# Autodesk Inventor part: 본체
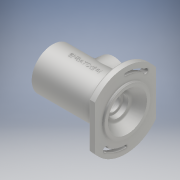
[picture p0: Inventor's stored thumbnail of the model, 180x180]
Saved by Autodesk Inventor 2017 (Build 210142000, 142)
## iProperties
Part Number: 본체
Material: 알루미늄 6061
Document SubType Name: Modeling
Designer: MRC
Density: 2.7 g/cm^3
Appearance: 알루미늄 - 평지
Author: MRC
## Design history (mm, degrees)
sketch "스케치1"
  geometry: L1 (47, 33.985)-(47, -33.985); L2 (-47, -33.985)-(-47, 33.985); A1 r 58 centre (0, 0) between (47, 33.985) and (-47, 33.985); A2 r 58 centre (0, 0) between (-47, -33.985) and (47, -33.985); 1 further point
  constraints: 4 end point, 4 point on circle, 2 centre point, 1 coincident, 1 parallel, 1 vertical
  dimensions: "d3" = 58 radius of A2; "d4" = 58 radius of A1; "d5" = 94 distance between parallel lines of L1 L2; "d6" = 47 distance from line of point (0, 0) L1
extrude "돌출1" new body sketch "스케치1" distance "d7" = 10; taper "d8" = 0 deg
sketch "스케치2"
  geometry: L1 (33.985, -47)-(-33.985, -47) reference; L2 (-33.985, 47)-(33.985, 47) reference; C1 r 36 at (0, 0); A1 r 58 centre (0, 0) between (33.985, -47) and (33.985, 47) reference; A2 r 58 centre (0, 0) between (-33.985, 47) and (-33.985, -47) reference; 1 further point
  constraints: 1 centre point, 1 coincident
  dimensions: "d9" = 72 diameter of C1
extrude "돌출2" join sketch "스케치2" distance "d10" = 3; taper "d11" = 0 deg
chamfer "모따기1" distance "d26" = 1; stored, may be unused: second distance "d27" = 2, angle "d28" = 45 deg
sketch "스케치4"
  geometry: L1 (-33.985, -47)-(33.985, -47) reference; L2 (33.985, 47)-(-33.985, 47) reference; C1 r 32 at (0, 0); A1 r 58 centre (0, 0) between (33.985, -47) and (33.985, 47) reference; A2 r 58 centre (0, 0) between (-33.985, 47) and (-33.985, -47) reference; 1 further point
  constraints: 1 centre point, 1 coincident
  dimensions: "d29" = 64 diameter of C1
extrude "돌출4" join sketch "스케치4" distance "d30" = 102; taper "d31" = 0 deg
fillet "모깎기1" dims "d32" = 3
node "작업 평면1"
node "작업 평면2"
sketch "스케치10"
  geometry: L1 (3, 35)-(3, -35) reference; L2 (3, 0)-(-112, 0); L3 (3, 30)-(-9.744, 20.897); L4 (-11, 18.456)-(-11, 15.404); L5 (-11.7, 15)-(-17.8, 15); L6 (-18.3, 14.5)-(-18.3, 11); L7 (-18.3, 11)-(-21, 11); L8 (-21, 11)-(-21, 12); L9 (-37, 18.5)-(-37, 24); L10 (-47.665, 26.047)-(-47.665, 25.836); L11 (-40, 27)-(-72, 27); L12 (-75, 24)-(-75, 18.5); L13 (-76, 17.5)-(-86, 17.5); L14 (-86, 17.5)-(-86, 18.5); L15 (-86, 18.5)-(-87.75, 18.5); L16 (-87.75, 18.5)-(-87.75, 17.5); L17 (-87.75, 17.5)-(-89, 17.5); L18 (-90, 18.5)-(-90, 19.5); L19 (-93, 22.5)-(-101, 22.5); L20 (-101, 22.5)-(-101, 24); L21 (-101, 24)-(-104, 24); L22 (-104, 24)-(-104, 22.5); L23 (-104, 22.5)-(-112, 22.5); L24 (-112, 32)-(-112, -32) reference; L25 (-11.7, 15)-(-11, 15.404); L26 (-76, 17.5)-(-75, 18.5); L27 (-89, 17.5)-(-90, 18.5); L28 (-112, 22.5)-(-112, 0); L29 (3, 30)-(3, 0); L30 (2, -36)-(2, 36) reference; L31 (-24, 15)-(-26, 15); L32 (-26, 15)-(-26, 16.9); L33 (-26.6, 17.5)-(-36, 17.5); L34 (-37, 18.5)-(-36, 17.5); A1 r 3 centre (-8, 18.456) between (-9.744, 20.897) and (-11, 18.456); A2 r 0.5 centre (-17.8, 14.5) between (-17.8, 15) and (-18.3, 14.5); A3 r 3 centre (-24, 12) between (-21, 12) and (-24, 15); A4 r 3 centre (-40, 24) between (-37, 24) and (-40, 27); A5 r 3 centre (-72, 24) between (-72, 27) and (-75, 24); A6 r 3 centre (-93, 19.5) between (-90, 19.5) and (-93, 22.5); A7 r 0.6 centre (-26.6, 16.9) between (-26, 16.9) and (-26.6, 17.5); 12 further points
  constraints: 62 end point, 24 point on line, 15 perpendicular, 14 point on circle, 13 tangent, 7 centre point, 4 horizontal, 2 vertical, 1 equal radius, 1 midpoint, 1 parallel
  dimensions: "d45" = 60 diameter of L3.start L2; "d46" = 40 diameter of point (-11, 20) L2; "d47" = 14 horizontal distance of point (-11, 20) L3.start; "d48" = 115 distance of L2.start L2.end; "d49" = 30 diameter of L5 L2; "d50" = 22 diameter of L7 L2; "d51" = 7.3 distance of point (-11, 15) point (-18.3, 15); "d55" = 54 diameter of L11 L2; "d57" = 35 diameter of L13 L2; "d58" = 11 distance of point (-75, 17.5) L13.end; "d59" = 1.75 distance of L14.end L15.end; "d60" = 37 diameter of L15 L2; "d61" = 4 distance between parallel lines of L18 L14; "d62" = 45 diameter of L19 L2; "d63" = 48 diameter of L21 L2; "d64" = 3 distance between parallel lines of L20 L22; "d65" = 8 distance from line of L22 L23.end; "d66" = 45 diameter of L23 L2; "d67" = 3 radius of A1; "d68" = 0.5 radius of A2; "d69" = 0.7 distance of L5.start point (-11, 15); "d70" = 30 deg angle of L5 L25; "d71" = 3 radius of A3; "d74" = 3 radius of A4 (derived); "d75" = 1 distance of L13.start point (-75, 17.5); "d76" = 1 distance of L12.end point (-75, 17.5) (= d75); "d77" = 1 distance of L17.end point (-90, 17.5) (= d75); "d78" = 1 distance of L18.start point (-90, 17.5) (= d77); "d79" = 3 radius of A6 (derived); "d148" = 5 distance between parallel lines of L8 L32; "d149" = 11 distance between parallel lines of L32 L9; "d150" = 29 distance between parallel lines of L1 L32; "d151" = 30 diameter of L31 L2; "d152" = 35 diameter of L33 L2; "d153" = 38 distance between parallel lines of L9 L12; "d155" = 0.6 radius of A7; "d156" = 1 distance of L9.start point (-37, 17.5); "d157" = 1 distance of L33.end point (-37, 17.5) (= d156)
revolve "회전1" sketch "스케치10" stored, may be unused: angle "d80" = 90 deg
feature "스레드1" dims "d81" = 10, "d82" = 0
node "작업 평면3"
sketch "스케치12"
  geometry: L1 (-3, -35)-(-3, 35) reference; L2 (112, -32)-(112, 32) reference; C1 r 25 at (56, 0); 1 further point
  constraints: 1 centre point
  dimensions: "d99" = 50 diameter of C1; "d154" = 56 distance from line of L2 C1.centre
extrude "돌출8" join sketch "스케치12" stored distance "d101" = 102; taper "d102" = 5 deg
hole "구멍2" diameter "d105" = 32; stored, may be unused: countersink angle "d109" = 90 deg, drill point angle "d111" = 118 deg; dims "d103" = 10, "d104" = 10, "d106" = 6, "d107" = 4, "d108" = 2, "d110" = 20
fillet "모깎기3" dims "d112" = 3
chamfer "모따기2" distance "d113" = 1; stored, may be unused: second distance "d114" = 2, angle "d115" = 45 deg
sketch "스케치13"
  geometry: C1 r 25 at (0, 0) reference; C2 r 17 at (0, 0) reference; A1 r 20.5 centre (0, 0) between (0, -20.5) and (0, 20.5); 1 further point
  constraints: 2 point on circle, 1 centre point, 1 coincident
  dimensions: "d116" = 41 diameter of A1
hole "구멍3" sketch "스케치13" at (0, -20.5), (0, 20.5) diameter "d117" = 2.621; stored, may be unused: countersink angle "d121" = 90 deg, drill point angle "d123" = 118 deg; dims "d118" = 6, "d119" = 4, "d120" = 2, "d122" = 8
sketch "스케치14"
  geometry: L1 (0, 0)-(-36.77, 30.854); L2 (0, 0)-(48, 0); L3 (0, 0)-(36.77, -30.854); L4 (0, 0)-(48, 0); L5 (0, 0)-(0, 37.337); L6 (0, 0)-(36.77, 30.854); A1 r 2.25 centre (36.77, 30.854) between (38.494, 32.3) and (35.047, 29.408); A2 r 45.75 centre (0, 0) between (45.75, 0) and (35.047, 29.408); A3 r 50.25 centre (0, 0) between (50.25, 0) and (38.494, 32.3); A4 r 2.25 centre (48, 0) between (45.75, 0) and (50.25, 0); A5 r 45.75 centre (0, 0) between (-45.75, 0) and (-35.047, -29.408); A6 r 50.25 centre (0, 0) between (-50.25, 0) and (-38.494, -32.3); A7 r 2.25 centre (-48, 0) between (-45.75, 0) and (-50.25, 0); A8 r 2.25 centre (-36.77, -30.854) between (-38.494, -32.3) and (-35.047, -29.408); 1 further point
  constraints: 16 point on circle, 12 end point, 8 centre point, 2 coincident, 2 equal length, 2 horizontal, 1 point on line, 1 symmetric about line, 1 vertical
  dimensions: "d125" = 140 deg angle of L2 L1; "d130" = 40 deg angle of L3 L4
extrude "돌출9" cut sketch "스케치14" distance "d131" = 102; taper "d132" = 0 deg
sketch "스케치16"
  geometry: L1 (-33, -44)-(33, -44) reference; L2 (33, 44)-(-33, 44) reference; C1 r 20.692 at (0, 0) reference; C2 r 35 at (0, 0) reference; C3 r 4 at (36.77, 30.854); C4 r 4 at (-36.77, -30.854); A1 r 2.25 centre (-48, 0) between (-45.75, 0) and (-50.25, 0) reference; A2 r 50.25 centre (0, 0) between (-50.25, 0) and (-38.494, -32.3) reference; A3 r 2.25 centre (-36.77, -30.854) between (-38.494, -32.3) and (-35.047, -29.408) reference; A4 r 45.75 centre (0, 0) between (-45.75, 0) and (-35.047, -29.408) reference; A5 r 45.75 centre (0, 0) between (45.75, 0) and (35.047, 29.408) reference; A6 r 2.25 centre (48, 0) between (45.75, 0) and (50.25, 0) reference; A7 r 50.25 centre (0, 0) between (50.25, 0) and (38.494, 32.3) reference; A8 r 2.25 centre (36.77, 30.854) between (38.494, 32.3) and (35.047, 29.408) reference; A9 r 55 centre (0, 0) between (33, -44) and (33, 44) reference; A10 r 55 centre (0, 0) between (-33, 44) and (-33, -44) reference; 1 further point
  constraints: 2 centre point, 2 coincident
  dimensions: "d141" = 8 diameter of C3; "d142" = 8 diameter of C4
extrude "돌출11" cut sketch "스케치16" stored distance "d143" = 4.4; taper "d144" = 0 deg
node "작업 평면4"
sketch "스케치17"
  geometry: L1 (10, 47)-(10, -47) reference; 3 further points
  constraints: 1 horizontal alignment, 1 midpoint, 1 other
  dimensions: "d145" = 62 distance from line of L1 point (-52, 0)
feature "엠보싱1" sketch "스케치17" dims "d3" = 58, "d4" = 58, "d5" = 94, "d6" = 47, "d146" = 0.5, "d147" = 0
sketch "스케치18"
  geometry: L1 (-33, -44)-(33, -44) reference; L2 (33, 44)-(-33, 44) reference; C1 r 20.692 at (0, 0) reference; C2 r 35 at (0, 0) reference; A1 r 4 centre (-36.77, -30.854) between (-40.58, -29.636) and (-37.033, -26.862) reference; A2 r 45.75 centre (0, 0) between (-45.75, 0) and (-37.033, -26.862) reference; A3 r 2.25 centre (-48, 0) between (-45.75, 0) and (-50.25, 0) reference; A4 r 50.25 centre (0, 0) between (-50.25, 0) and (-40.58, -29.636) reference; A5 r 4 centre (36.77, 30.854) between (40.58, 29.636) and (37.033, 26.862) reference; A6 r 45.75 centre (0, 0) between (45.75, 0) and (37.033, 26.862) reference; A7 r 2.25 centre (48, 0) between (45.75, 0) and (50.25, 0) reference; A8 r 50.25 centre (0, 0) between (50.25, 0) and (40.58, 29.636) reference; A9 r 55 centre (0, 0) between (33, -44) and (33, 44) reference; A10 r 55 centre (0, 0) between (-33, 44) and (-33, -44) reference; A11 r 4 centre (36.77, 30.854) between (39.834, 33.425) and (33.706, 28.283); A12 r 4 centre (48, 0) between (44, 0) and (52, 0); A13 r 4 centre (-48, 0) between (-44, 0) and (-52, 0); A14 r 4 centre (-36.77, -30.854) between (-39.834, -33.425) and (-33.706, -28.283); A15 r 52 centre (0, 0) between (-52, 0) and (-39.834, -33.425); A16 r 44 centre (0, 0) between (-44, 0) and (-33.706, -28.283); A17 r 52 centre (0, 0) between (52, 0) and (39.834, 33.425); A18 r 44 centre (0, 0) between (44, 0) and (33.706, 28.283); 1 further point
  constraints: 20 point on circle, 8 centre point, 5 coincident, 1 concentric
  dimensions: "d158" = 8 diameter of A12; "d159" = 8 diameter of A13
extrude "돌출12" cut sketch "스케치18" distance "d165" = 4.4; taper "d166" = 0 deg
node "솔리드1"
node "투영된 루프1"
node "투영된 루프2"
node "투영된 루프5"
node "절단 모서리 투영4"
node "절단 모서리 투영5"
other parameters: "d0" = 58, "d12" = 96, "d17" = 4, "d18" = 4, "d34" = -14, "d38" = 38, "d98" = 38, "d124" = 96, "d128" = 2.25, "d129" = 2.25, "d137" = 4, "d138" = 4, "d163" = 4, "d164" = 4
